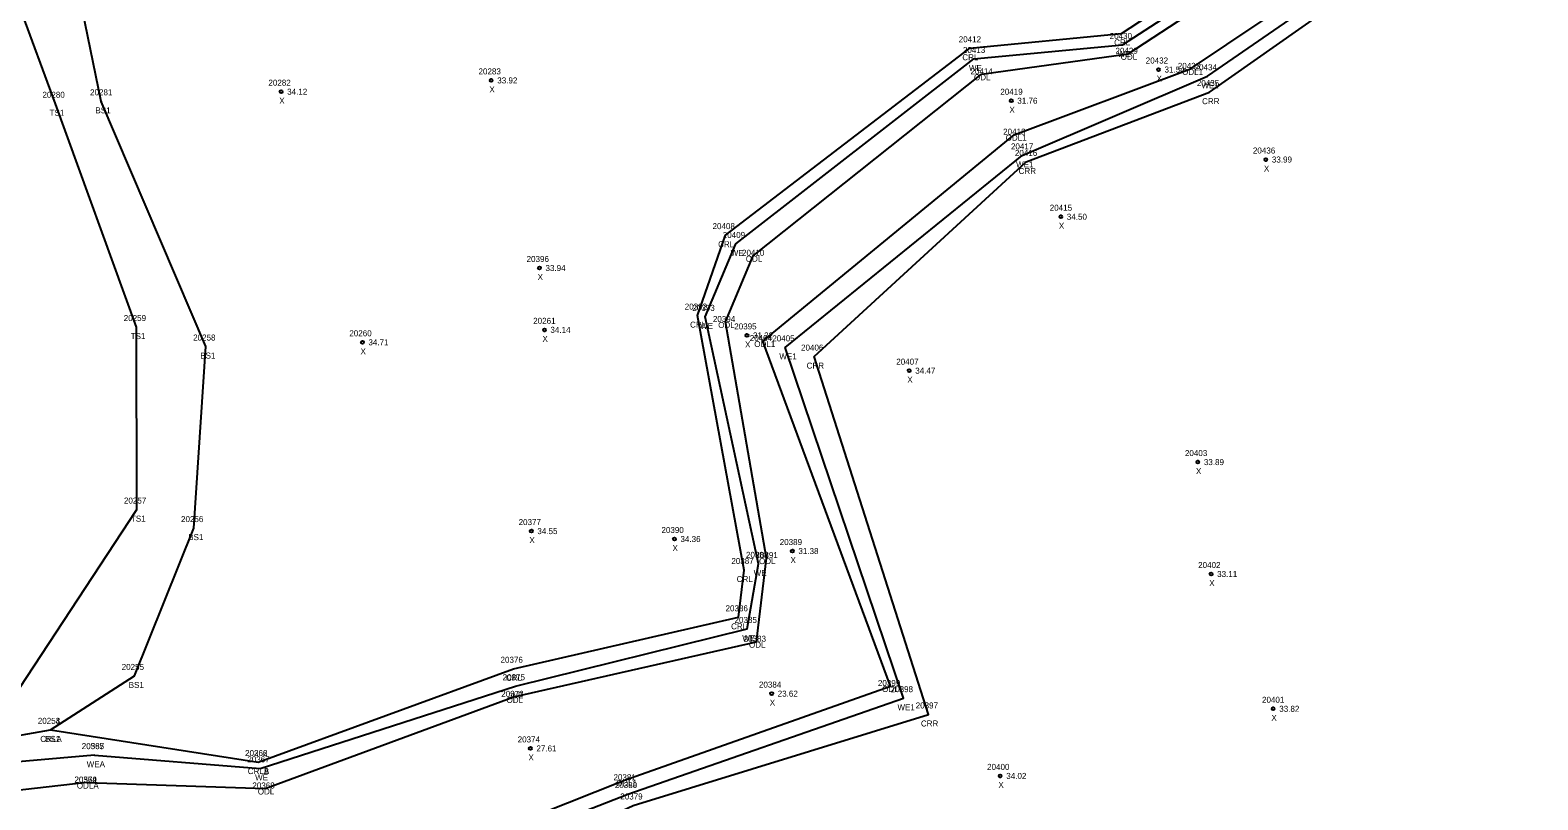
# Model space of a CAD drawing. Extents: x 2445178 to 2446260, y 791158 to 792318.
# Drawn here: x 2445746.6 to 2445997.4, y 791810 to 791938.1 of the extents above; entities that cross this region are included whole.
import ezdxf

# ---------------------------------------------------------------- set-up
doc = ezdxf.new("R2010")
doc.units = 0
for name, color, linetype in [('RD_DTM_BkLn2', 7, 'Continuous'), ('RD_EX_H2O', 7, 'Continuous'), ('RD_EX_H2O_txCode', 7, 'Continuous'), ('RD_Sketch8', 7, 'Continuous'), ('RD_SMD_Locator', 7, 'Continuous'), ('RD_SMD_Misc', 7, 'Continuous')]:
    doc.layers.add(name, color=color, linetype=linetype)

msp = doc.modelspace()

# ---------------------------------------------------------------- linework, layer by layer
at = {"layer": 'RD_DTM_BkLn2'}
for points in [[(2445723.15, 791827.97), (2445742.38, 791824.93), (2445764.31, 791858.33), (2445764.27, 791888.69), (2445750.79, 791925.83), (2445727.01, 791990.21), (2445728.86, 792017.77)], [(2445721.97, 791816.74), (2445749.98, 791821.69), (2445763.92, 791830.66), (2445773.82, 791855.25), (2445775.82, 791885.45), (2445758.38, 791926.24), (2445744.75, 791992.74), (2445740.15, 792016.85)]]:
    msp.add_lwpolyline(points, dxfattribs=at)
at = {"layer": 'RD_EX_H2O'}
for points in [[(2445749.98, 791821.69), (2445784.5, 791816.33), (2445784.5, 791816.33), (2445826.97, 791831.85), (2445864.4, 791840.41), (2445865.35, 791848.28), (2445857.59, 791890.6), (2445862.25, 791903.98), (2445902.88, 791935.07), (2445928.13, 791937.54), (2445982.7, 791973.27), (2446006.36, 791974.66), (2446055.29, 791944.59), (2446112.86, 791944.82), (2446116.06, 791949.26), (2446125.53, 791975.87), (2446156.76, 791972.15), (2446187.24, 792018.21)], [(2445757.3, 791817.48), (2445784.85, 791815.29), (2445827.3, 791828.95), (2445865.88, 791838.48), (2445867.77, 791849.3), (2445858.86, 791890.39), (2445863.96, 791902.52), (2445903.58, 791933.29), (2445928.32, 791935.62), (2445983.75, 791971.59), (2446005.28, 791972.74), (2446055.03, 791943.12), (2446113.69, 791943.23), (2446117.06, 791949.31), (2446126.55, 791974.16), (2446158.67, 791970.49), (2446188.67, 792015.57)], [(2445756.08, 791812.92), (2445785.69, 791811.94), (2445827.07, 791827.18), (2445867.4, 791836.35), (2445869.07, 791850.26), (2445862.28, 791889.54), (2445866.87, 791900.55), (2445904.83, 791930.74), (2445929.24, 791934.15), (2445984.41, 791970.25), (2446004.58, 791971.21), (2446054.77, 791941.67), (2446115.62, 791938.17), (2446120.64, 791945.97), (2446127.84, 791972.01), (2446160.1, 791969.34), (2446190.11, 792012.94)], [(2445748.32, 791780.49), (2445788.24, 791788.44), (2445846, 791811.01), (2445891.85, 791826.96), (2445872.2, 791885.31), (2445911.58, 791917.24), (2445942.41, 791930.41), (2445989.95, 791963.2), (2446004.43, 791957.67), (2446037.13, 791928.19), (2446062.94, 791924.63), (2446122.42, 791925.89), (2446133.98, 791956.62), (2446163.05, 791958.48), (2446202.11, 792005.16)], [(2445752.43, 791785.31), (2445788.27, 791790.61), (2445845.46, 791813.31), (2445889.72, 791828.98), (2445868.44, 791886.37), (2445910.27, 791920.69), (2445939.62, 791931.64), (2445988.31, 791964.33), (2446005.31, 791961.03), (2446034.89, 791932.66), (2446061.86, 791927.42), (2446120.16, 791928.99), (2446131.56, 791958.98), (2446161.23, 791962.03), (2446198.32, 792006.02)], [(2445746.88, 791778.25), (2445790.91, 791782.86), (2445846.87, 791809.11), (2445896.01, 791824.25), (2445877, 791883.78), (2445912.26, 791916.16), (2445942.78, 791927.77), (2445991.6, 791962.06), (2446003.69, 791956.06), (2446036.32, 791927.07), (2446060.96, 791923.67), (2446122.97, 791923.97), (2446134.24, 791956.18), (2446163.21, 791958.01), (2446202.51, 792004.24)], [(2445757.3, 791817.48), (2445724.23, 791814.58), (2445698.23, 791807.38), (2445689.87, 791803.29), (2445658, 791800.52), (2445641.81, 791830.07), (2445642.32, 791839.59), (2445634.31, 791862.06), (2445625.81, 791909.02), (2445601.16, 791980.42)], [(2445756.08, 791812.92), (2445698.14, 791806.34), (2445651.88, 791781.68), (2445605.82, 791776.55)]]:
    msp.add_lwpolyline(points, dxfattribs=at)
at = {"layer": 'RD_SMD_Locator'}
for centre, radius in [((2445928.13, 791937.54), 0.001), ((2445902.88, 791935.07), 0.001), ((2445928.32, 791935.62), 0.001), ((2445903.58, 791933.29), 0.001), ((2445929.24, 791934.15), 0.001), ((2445823.29, 791929.72), 0.25), ((2445904.83, 791930.74), 0.001), ((2445934.28, 791931.53), 0.25), ((2445939.62, 791931.64), 0.001), ((2445942.41, 791930.41), 0.001), ((2445788.34, 791927.84), 0.25), ((2445942.78, 791927.77), 0.001), ((2445750.79, 791925.83), 0.001), ((2445758.38, 791926.24), 0.001), ((2445909.8, 791926.34), 0.25), ((2445910.27, 791920.69), 0.001), ((2445911.58, 791917.24), 0.001), ((2445912.26, 791916.16), 0.001), ((2445952.14, 791916.56), 0.25), ((2445918.03, 791907.04), 0.25), ((2445862.25, 791903.98), 0.001), ((2445863.96, 791902.52), 0.001), ((2445866.87, 791900.55), 0.001), ((2445831.31, 791898.52), 0.25), ((2445857.59, 791890.6), 0.001), ((2445858.86, 791890.39), 0.001), ((2445764.27, 791888.69), 0.001), ((2445832.13, 791888.23), 0.25), ((2445862.28, 791889.54), 0.001), ((2445865.83, 791887.3), 0.25), ((2445775.82, 791885.45), 0.001), ((2445801.86, 791886.16), 0.25), ((2445868.44, 791886.37), 0.001), ((2445872.2, 791885.31), 0.001), ((2445877, 791883.78), 0.001), ((2445892.82, 791881.44), 0.25), ((2445940.83, 791866.23), 0.25), ((2445764.31, 791858.33), 0.001), ((2445773.82, 791855.25), 0.001), ((2445829.96, 791854.75), 0.25), ((2445853.76, 791853.43), 0.25), ((2445869.07, 791850.26), 0.001), ((2445873.38, 791851.43), 0.25), ((2445865.35, 791848.28), 0.001), ((2445867.77, 791849.3), 0.001), ((2445943.04, 791847.61), 0.25), ((2445864.4, 791840.41), 0.001), ((2445865.88, 791838.48), 0.001), ((2445867.4, 791836.35), 0.001), ((2445763.92, 791830.66), 0.001), ((2445826.97, 791831.85), 0.001), ((2445827.07, 791827.18), 0.001), ((2445827.3, 791828.95), 0.001), ((2445869.94, 791827.72), 0.25), ((2445889.72, 791828.98), 0.001), ((2445891.85, 791826.96), 0.001), ((2445953.37, 791825.19), 0.25), ((2445896.01, 791824.25), 0.001), ((2445749.98, 791821.69), 0.001), ((2445749.98, 791821.69), 0.001), ((2445757.3, 791817.48), 0.001), ((2445757.3, 791817.48), 0.001), ((2445829.8, 791818.6), 0.25), ((2445784.5, 791816.33), 0.001), ((2445784.5, 791816.33), 0.001), ((2445784.85, 791815.29), 0.001), ((2445756.08, 791812.92), 0.001), ((2445756.08, 791812.92), 0.001), ((2445845.46, 791813.31), 0.001), ((2445907.96, 791814.03), 0.25), ((2445785.69, 791811.94), 0.001), ((2445846, 791811.01), 0.001)]:
    msp.add_circle(centre, radius, dxfattribs=at)

# ---------------------------------------------------------------- texts
at = {"layer": 'RD_EX_H2O_txCode'}
for s, p in [('20430', (2445926.16, 791936.62)), ('20412', (2445901.05, 791936.07)), ('20413', (2445901.75, 791934.29)), ('CRL', (2445926.9, 791935.54)), ('20429', (2445927.12, 791934.15)), ('CRL', (2445901.65, 791933.07)), ('WE', (2445927.48, 791933.62)), ('ODL', (2445927.99, 791933.15)), ('20433', (2445937.5, 791931.64)), ('20434', (2445940.29, 791931.41)), ('WE', (2445902.74, 791931.29)), ('20414', (2445903, 791930.74)), ('ODL', (2445903.59, 791929.74)), ('ODL1', (2445938.21, 791930.64)), ('20435', (2445940.66, 791928.77)), ('WE1', (2445941.42, 791928.41)), ('CRR', (2445941.53, 791925.77)), ('20418', (2445908.44, 791920.69)), ('ODL1', (2445908.86, 791919.69)), ('20417', (2445909.74, 791918.24)), ('20416', (2445910.4, 791917.16)), ('WE1', (2445910.59, 791915.24)), ('CRR', (2445911.01, 791914.16)), ('20408', (2445860.1, 791904.98)), ('CRL', (2445861.03, 791901.98)), ('20409', (2445861.8, 791903.52)), ('WE', (2445863.12, 791900.52)), ('20410', (2445865, 791900.55)), ('ODL', (2445865.63, 791899.55)), ('20392', (2445855.47, 791891.6)), ('20393', (2445856.75, 791891.39)), ('20394', (2445860.16, 791889.54)), ('CRL', (2445856.36, 791888.6)), ('WE', (2445858.03, 791888.39)), ('ODL', (2445861.04, 791888.54)), ('20404', (2445866.29, 791886.37)), ('20405', (2445870.04, 791886.31)), ('ODL1', (2445867.04, 791885.37)), ('20406', (2445874.82, 791884.78)), ('WE1', (2445871.21, 791883.31)), ('CRR', (2445875.75, 791881.78)), ('20387', (2445863.23, 791849.28)), ('20388', (2445865.66, 791850.3)), ('20391', (2445867.24, 791850.26)), ('ODL', (2445867.83, 791849.26)), ('CRL', (2445864.12, 791846.28)), ('WE', (2445866.94, 791847.3)), ('20386', (2445862.26, 791841.41)), ('20385', (2445863.76, 791839.48)), ('CRL', (2445863.18, 791838.41)), ('WE', (2445865.04, 791836.48)), ('20383', (2445865.28, 791836.35)), ('ODL', (2445866.16, 791835.35)), ('20376', (2445824.83, 791832.85)), ('20375', (2445825.18, 791829.95)), ('CRL', (2445825.74, 791829.85)), ('20399', (2445887.61, 791828.98)), ('20373', (2445824.95, 791827.18)), ('ODL', (2445825.83, 791826.18)), ('WE', (2445826.46, 791826.95)), ('ODL1', (2445888.31, 791827.98)), ('20398', (2445889.73, 791827.96)), ('WE1', (2445890.86, 791824.96)), ('20397', (2445893.89, 791825.25)), ('20254', (2445747.86, 791822.69)), ('CRR', (2445894.76, 791822.25)), ('CRLA', (2445748.27, 791819.69)), ('20365', (2445755.16, 791818.48)), ('20587', (2445755.18, 791818.48)), ('20366', (2445782.33, 791817.33)), ('20262', (2445782.35, 791817.33)), ('20367', (2445782.71, 791816.29)), ('WEA', (2445755.99, 791815.48)), ('WEA', (2445755.99, 791815.48)), ('CRLA', (2445782.78, 791814.33)), ('CRLB', (2445782.79, 791814.33)), ('20364', (2445753.94, 791812.92)), ('20579', (2445753.97, 791812.92)), ('ODLA', (2445754.35, 791811.92)), ('ODLA', (2445754.35, 791811.92)), ('20368', (2445783.55, 791811.94)), ('WE', (2445784.01, 791813.29)), ('20381', (2445843.62, 791813.31)), ('20380', (2445843.84, 791812.01)), ('ODL1', (2445844.05, 791812.31)), ('ODL', (2445784.45, 791810.94)), ('20379', (2445844.75, 791810.11))]:
    msp.add_text(s, height=1, dxfattribs=at).set_placement(p)
at = {"layer": 'RD_Sketch8'}
for s, p in [('20432', (2445932.16, 791932.53)), ('20282', (2445786.22, 791928.84)), ('20283', (2445821.17, 791930.72)), ('33.92', (2445824.29, 791929.22)), ('X', (2445933.96, 791929.53)), ('31.54', (2445935.28, 791931.03)), ('34.12', (2445789.34, 791927.34)), ('X', (2445822.98, 791927.72)), ('20419', (2445907.97, 791927.34)), ('X', (2445788.03, 791925.84)), ('X', (2445909.49, 791924.34)), ('31.76', (2445910.8, 791925.84)), ('20436', (2445949.99, 791917.56)), ('X', (2445951.82, 791914.56)), ('33.99', (2445953.14, 791916.06)), ('20415', (2445916.19, 791908.04)), ('34.50', (2445919.03, 791906.54)), ('X', (2445917.71, 791905.04)), ('20396', (2445829.17, 791899.52)), ('X', (2445831, 791896.52)), ('33.94', (2445832.31, 791898.02)), ('20261', (2445830.27, 791889.23)), ('20260', (2445799.68, 791887.16)), ('X', (2445831.81, 791886.23)), ('34.14', (2445833.13, 791887.73)), ('20395', (2445863.71, 791888.3)), ('31.22', (2445866.83, 791886.8)), ('X', (2445801.54, 791884.16)), ('34.71', (2445802.86, 791885.66)), ('X', (2445865.51, 791885.3)), ('20407', (2445890.66, 791882.44)), ('X', (2445892.5, 791879.44)), ('34.47', (2445893.82, 791880.94)), ('20403', (2445938.68, 791867.23)), ('X', (2445940.52, 791864.23)), ('33.89', (2445941.83, 791865.73)), ('20377', (2445827.84, 791855.75)), ('34.55', (2445830.96, 791854.25)), ('20390', (2445851.6, 791854.43)), ('X', (2445829.64, 791852.75)), ('X', (2445853.44, 791851.43)), ('34.36', (2445854.76, 791852.93)), ('20389', (2445871.27, 791852.43)), ('X', (2445873.07, 791849.43)), ('31.38', (2445874.38, 791850.93)), ('20402', (2445940.88, 791848.61)), ('33.11', (2445944.04, 791847.11)), ('X', (2445942.72, 791845.61)), ('20384', (2445867.82, 791828.72)), ('23.62', (2445870.94, 791827.22)), ('20401', (2445951.5, 791826.19)), ('X', (2445869.62, 791825.72)), ('33.82', (2445954.37, 791824.69)), ('X', (2445953.06, 791823.19)), ('20374', (2445827.68, 791819.6)), ('X', (2445829.48, 791816.6)), ('27.61', (2445830.8, 791818.1)), ('20400', (2445905.77, 791815.03)), ('34.02', (2445908.96, 791813.53)), ('X', (2445907.65, 791812.03))]:
    msp.add_text(s, height=1, dxfattribs=at).set_placement(p)
at = {"layer": 'RD_SMD_Misc'}
for s, p in [('20280', (2445748.63, 791926.83)), ('20281', (2445756.55, 791927.24)), ('TS1', (2445749.83, 791923.83)), ('BS1', (2445757.44, 791924.24)), ('20259', (2445762.15, 791889.69)), ('TS1', (2445763.31, 791886.69)), ('20258', (2445773.7, 791886.45)), ('BS1', (2445774.88, 791883.45)), ('20257', (2445762.19, 791859.33)), ('TS1', (2445763.35, 791856.33)), ('20256', (2445771.68, 791856.25)), ('BS1', (2445772.88, 791853.25)), ('20255', (2445761.81, 791831.66)), ('BS1', (2445762.98, 791828.66)), ('20253', (2445747.86, 791822.69)), ('BS1', (2445749.04, 791819.69))]:
    msp.add_text(s, height=1, dxfattribs=at).set_placement(p)

doc.saveas('drawing.dxf')
